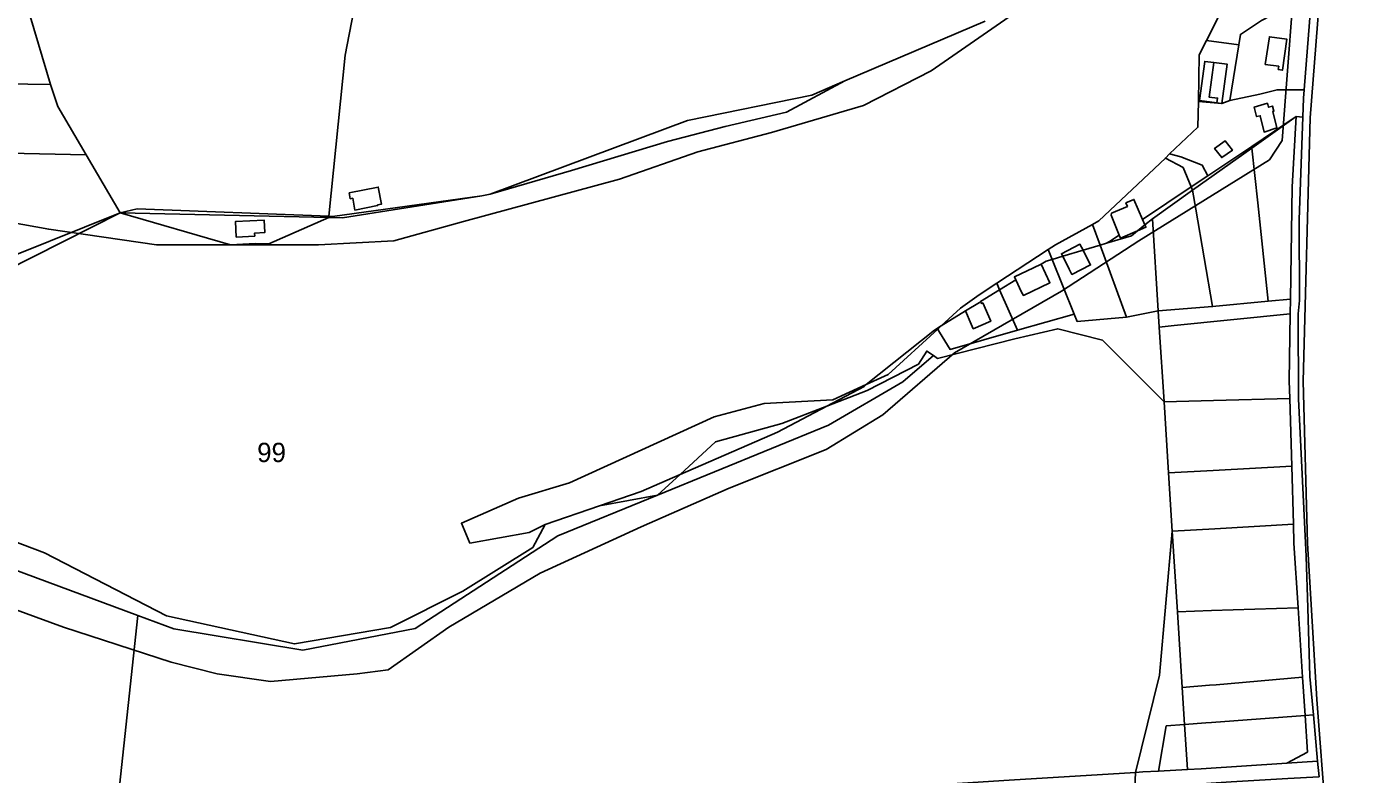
# Model space of a CAD drawing. Extents: x -537068 to -534056, y -1176840 to -1172401.
# Drawn here: x -535510.5 to -535168.8, y -1176578.1 to -1176384.5 of the extents above; entities that cross this region are included whole.
import ezdxf

# ---------------------------------------------------------------- set-up
doc = ezdxf.new("R2010")
doc.units = 0
for name, color, linetype in [('95560013', 7, 'Continuous'), ('95630013', 7, 'Continuous'), ('95640013', 7, 'Continuous'), ('95660013', 7, 'Continuous')]:
    doc.layers.add(name, color=color, linetype=linetype)

msp = doc.modelspace()

# ---------------------------------------------------------------- linework, layer by layer
at = {"layer": '95560013'}
for points in [[(-535481.85, -1176431.69), (-535486.24, -1176432.72), (-535495.01, -1176417.7), (-535502.3, -1176405.2), (-535504.23, -1176399.52), (-535511.62, -1176374.55), (-535501.24, -1176369.64), (-535467.02, -1176363.71), (-535431.92, -1176357.62), (-535424.35, -1176355.69), (-535420.92, -1176355.35), (-535427.94, -1176391.96), (-535432.2, -1176433.64)], [(-535511.62, -1176374.55), (-535504.23, -1176399.52), (-535562.67, -1176398.68)], [(-535495.01, -1176417.7), (-535595.37, -1176415.54), (-535577.58, -1176405.73), (-535562.67, -1176398.68), (-535504.23, -1176399.52), (-535502.3, -1176405.2)], [(-535495.01, -1176417.7), (-535486.24, -1176432.72), (-535522.77, -1176447.43), (-535520.14, -1176434.4), (-535519.96, -1176430.27), (-535571.1, -1176424.91), (-535618.53, -1176428.31), (-535595.37, -1176415.54)], [(-535419.44, -1176426.07), (-535426.94, -1176427.6), (-535426.66, -1176429.1), (-535426.01, -1176428.98), (-535425.44, -1176432.03), (-535419.58, -1176430.86), (-535419.61, -1176430.71), (-535418.55, -1176430.5)], [(-535428.71, -1176434.07), (-535432.24, -1176433.99), (-535432.2, -1176433.64), (-535431.24, -1176433.68), (-535392.59, -1176428.31)], [(-535523.63, -1176451.66), (-535522.77, -1176447.43), (-535486.24, -1176432.72)], [(-535481.85, -1176431.69), (-535432.2, -1176433.64), (-535432.24, -1176433.99), (-535486.24, -1176432.72)]]:
    msp.add_lwpolyline(points, close=True, dxfattribs=at)
msp.add_lwpolyline([(-535262.36, -1176383.13), (-535298.7, -1176398.63), (-535307.24, -1176402.28), (-535339.41, -1176408.87), (-535390.42, -1176427.96), (-535392.59, -1176428.31), (-535431.24, -1176433.68), (-535432.2, -1176433.64), (-535427.94, -1176391.96), (-535420.92, -1176355.35)], dxfattribs=at)
at = {"layer": '95630013'}
for points in [[(-535201.88, -1176381.84), (-535205.08, -1176388.14), (-535206.96, -1176391.84), (-535207.19, -1176403.93), (-535207.32, -1176410.61), (-535214.63, -1176417.52), (-535215.74, -1176418.57), (-535232.97, -1176434.86), (-535234.57, -1176435.74), (-535244.18, -1176441.03), (-535246.07, -1176442.27), (-535259.38, -1176450.99), (-535263.89, -1176453.95), (-535268.77, -1176457.43), (-535273.76, -1176462.03), (-535275.52, -1176463.11), (-535293.14, -1176477.21), (-535301.82, -1176481.16), (-535319.57, -1176482.1), (-535332.49, -1176485.54), (-535369.95, -1176502.58), (-535383.1, -1176506.55), (-535397.91, -1176513.07), (-535395.69, -1176518.21), (-535380.34, -1176515.47), (-535376.22, -1176513.36), (-535379.46, -1176519.34), (-535397.53, -1176530.66), (-535416.25, -1176540.06), (-535441.1, -1176544.28), (-535474.22, -1176537.07), (-535505.76, -1176520.73), (-535533.2, -1176510.4)], [(-535523.63, -1176451.66), (-535486.24, -1176432.72), (-535457.69, -1176441.02), (-535451.28, -1176440.64), (-535447.75, -1176440.73), (-535432.24, -1176433.99), (-535428.71, -1176434.07), (-535392.59, -1176428.31), (-535390.42, -1176427.96), (-535369.38, -1176421.83), (-535344.59, -1176414.25), (-535329.68, -1176410.43), (-535313.78, -1176406.71), (-535298.7, -1176398.63), (-535262.36, -1176383.13)], [(-535533.2, -1176510.4), (-535505.76, -1176520.73), (-535474.22, -1176537.07), (-535441.1, -1176544.28), (-535416.25, -1176540.06), (-535397.53, -1176530.66), (-535379.46, -1176519.34), (-535376.22, -1176513.36), (-535362.19, -1176508.54), (-535347.18, -1176505.79), (-535372.98, -1176516.36), (-535409.88, -1176540.34), (-535438.98, -1176545.89), (-535472.29, -1176540.41), (-535481.66, -1176536.93), (-535537.73, -1176516.12)]]:
    msp.add_lwpolyline(points, dxfattribs=at)
for points in [[(-535339.41, -1176408.87), (-535307.24, -1176402.28), (-535298.7, -1176398.63), (-535313.78, -1176406.71), (-535329.68, -1176410.43), (-535344.59, -1176414.25), (-535369.38, -1176421.83), (-535390.42, -1176427.96)], [(-535447.75, -1176440.73), (-535451.28, -1176440.64), (-535457.69, -1176441.02), (-535486.24, -1176432.72), (-535432.24, -1176433.99)], [(-535451.37, -1176438.77), (-535451.41, -1176437.98), (-535448.79, -1176437.86), (-535448.97, -1176434.63), (-535456.32, -1176434.98), (-535456.16, -1176439.02)], [(-535481.66, -1176536.93), (-535472.29, -1176540.41), (-535438.98, -1176545.89), (-535409.88, -1176540.34), (-535372.98, -1176516.36), (-535347.18, -1176505.79), (-535302.92, -1176487.67), (-535283.68, -1176476.52), (-535275.78, -1176469.69), (-535274.71, -1176470.43), (-535254.68, -1176465.39), (-535243.6, -1176462.73), (-535231.98, -1176465.74), (-535216.08, -1176481.68), (-535214.91, -1176500.06), (-535213.95, -1176515.16), (-535217.22, -1176552.4), (-535223.43, -1176577.55), (-535256.14, -1176579.59), (-535277.65, -1176580.92), (-535296.77, -1176582.11), (-535421.85, -1176589.87), (-535487.75, -1176593.96)], [(-535293.14, -1176477.21), (-535275.52, -1176463.11), (-535273.76, -1176462.03), (-535274.65, -1176462.84), (-535287.44, -1176474.62)], [(-535347.18, -1176505.79), (-535341.33, -1176500.46), (-535316.14, -1176489.48), (-535303.38, -1176482.75), (-535292.89, -1176478.68), (-535279.66, -1176471.94), (-535277.47, -1176468.51), (-535275.78, -1176469.69), (-535283.68, -1176476.52), (-535302.92, -1176487.67)], [(-535315, -1176487.27), (-535303.38, -1176482.75), (-535316.14, -1176489.48), (-535341.33, -1176500.46), (-535332.11, -1176492.04)], [(-535611.19, -1176513.92), (-535537.73, -1176516.12), (-535481.66, -1176536.93), (-535487.75, -1176593.96), (-535547.63, -1176597.67), (-535617.46, -1176602.04), (-535616.99, -1176606.16), (-535547.67, -1176601.79), (-535488.18, -1176598.05), (-535496.14, -1176672.63), (-535510.43, -1176678.69), (-535538.74, -1176685.61), (-535560.3, -1176696.02), (-535567.5, -1176700.1), (-535587.32, -1176690.88), (-535593.03, -1176689.8), (-535608.35, -1176682.47), (-535631.81, -1176671.18), (-535642.41, -1176641.9), (-535625.41, -1176591.75), (-535625.2, -1176543.89)], [(-535616.99, -1176606.16), (-535617.46, -1176602.04), (-535547.63, -1176597.67), (-535487.75, -1176593.96), (-535421.85, -1176589.87), (-535296.77, -1176582.11), (-535277.65, -1176580.92), (-535256.14, -1176579.59), (-535223.43, -1176577.55), (-535223.63, -1176581.58), (-535224.99, -1176581.66), (-535236.23, -1176582.36), (-535246.06, -1176582.97), (-535421.6, -1176593.86), (-535488.18, -1176598.05), (-535547.67, -1176601.79)]]:
    msp.add_lwpolyline(points, close=True, dxfattribs=at)
at = {"layer": '95640013'}
for points in [[(-535168.84, -1176287.98), (-535178.27, -1176408.14), (-535180.12, -1176476.29), (-535178.97, -1176518.25), (-535176.57, -1176558.65), (-535171.92, -1176619.39)], [(-535175.97, -1176578.68), (-535176.34, -1176574.66), (-535177.43, -1176562.68), (-535178.34, -1176552.77), (-535178.9, -1176534.97), (-535179.3, -1176521.64), (-535181.32, -1176480.84), (-535181.35, -1176458.92), (-535181.06, -1176455.43), (-535181.08, -1176434.43), (-535180.14, -1176407.98), (-535179.97, -1176403.1), (-535179.8, -1176400.89), (-535177.92, -1176376.77)]]:
    msp.add_lwpolyline(points, dxfattribs=at)
for points in [[(-535177.92, -1176376.77), (-535188.56, -1176381.77), (-535190.84, -1176383), (-535196.3, -1176386.58), (-535196.74, -1176389.27), (-535205.08, -1176388.14), (-535201.88, -1176381.84), (-535191.43, -1176380.38), (-535189.63, -1176379.33), (-535177.7, -1176373.96)], [(-535196.74, -1176389.27), (-535196.3, -1176386.58), (-535190.84, -1176383), (-535188.56, -1176381.77), (-535177.92, -1176376.77), (-535179.8, -1176400.89), (-535182.66, -1176400.88), (-535186.83, -1176400.9), (-535191.31, -1176402.04), (-535199.02, -1176403.71)], [(-535205.08, -1176388.14), (-535196.74, -1176389.27), (-535199.02, -1176403.71), (-535201.16, -1176404.46), (-535199.74, -1176394.28), (-535203.22, -1176393.84), (-535205.56, -1176393.55), (-535206.94, -1176403.67), (-535202.41, -1176404.29), (-535201.16, -1176404.46), (-535207.19, -1176403.93), (-535206.96, -1176391.84)], [(-535186.54, -1176395.62), (-535185.43, -1176395.86), (-535184.31, -1176387.78), (-535188.83, -1176387.17), (-535189.87, -1176394.33), (-535186.4, -1176394.8)], [(-535186.4, -1176394.8), (-535189.87, -1176394.33), (-535188.83, -1176387.17), (-535184.31, -1176387.78), (-535185.43, -1176395.86), (-535186.54, -1176395.62)], [(-535206.94, -1176403.67), (-535205.56, -1176393.55), (-535203.22, -1176393.84), (-535204.43, -1176402.78), (-535202.24, -1176403.07), (-535202.41, -1176404.29)], [(-535199.74, -1176394.28), (-535201.16, -1176404.46), (-535202.41, -1176404.29), (-535202.24, -1176403.07), (-535204.43, -1176402.78), (-535203.22, -1176393.84)], [(-535179.97, -1176403.1), (-535180.14, -1176407.98), (-535181.86, -1176407.84), (-535193.38, -1176415.55), (-535204.79, -1176423.18), (-535206.18, -1176420.42), (-535211.73, -1176418.24), (-535214.63, -1176417.52), (-535207.32, -1176410.61), (-535207.19, -1176403.93), (-535201.16, -1176404.46), (-535199.02, -1176403.71), (-535191.31, -1176402.04), (-535186.83, -1176400.9), (-535182.66, -1176400.88), (-535179.8, -1176400.89)], [(-535190.2, -1176411.86), (-535191.18, -1176407.62), (-535192.15, -1176407.84), (-535192.8, -1176405.44), (-535189.32, -1176404.38), (-535189.04, -1176405.43), (-535188.03, -1176405.11), (-535187.66, -1176406.43), (-535187.91, -1176406.5), (-535186.9, -1176410.78)], [(-535189.32, -1176404.38), (-535192.8, -1176405.44), (-535192.15, -1176407.84), (-535191.18, -1176407.62), (-535190.2, -1176411.86), (-535186.9, -1176410.78), (-535187.91, -1176406.5), (-535187.66, -1176406.43), (-535188.03, -1176405.11), (-535189.04, -1176405.43)], [(-535181.86, -1176407.84), (-535193.33, -1176415.99), (-535193.38, -1176415.55)], [(-535181.86, -1176407.84), (-535182.92, -1176426.05), (-535183.35, -1176455.05), (-535189.17, -1176455.61), (-535191.84, -1176430.14), (-535193.33, -1176415.99)], [(-535177.43, -1176562.68), (-535179.58, -1176562.84), (-535180.22, -1176552.91), (-535181.38, -1176534.99), (-535182.46, -1176518.26), (-535182.6, -1176513.31), (-535183.03, -1176498.34), (-535183.53, -1176480.82), (-535183.66, -1176476.24), (-535183.4, -1176458.9), (-535183.35, -1176455.05), (-535182.92, -1176426.05), (-535181.86, -1176407.84), (-535180.14, -1176407.98), (-535181.08, -1176434.43), (-535181.06, -1176455.43), (-535181.35, -1176458.92), (-535181.32, -1176480.84), (-535179.3, -1176521.64), (-535178.9, -1176534.97), (-535178.34, -1176552.77)], [(-535204.79, -1176423.18), (-535193.38, -1176415.55), (-535193.33, -1176415.99), (-535208.69, -1176426.9), (-535209.05, -1176426.04)], [(-535191.84, -1176430.14), (-535189.17, -1176455.61), (-535203.54, -1176456.99), (-535207.85, -1176431.83), (-535208.69, -1176426.9), (-535193.33, -1176415.99)], [(-535201.13, -1176418.47), (-535203.02, -1176416.07), (-535200.22, -1176414.13), (-535198.4, -1176416.55)], [(-535200.22, -1176414.13), (-535203.02, -1176416.07), (-535201.13, -1176418.47), (-535198.4, -1176416.55)], [(-535227.68, -1176438.5), (-535230.16, -1176440.16), (-535230.97, -1176440.62), (-535232.61, -1176441.11), (-535234.57, -1176435.74), (-535232.97, -1176434.86), (-535215.74, -1176418.57), (-535211.16, -1176421), (-535209.05, -1176426.04), (-535221.64, -1176434.46), (-535223.89, -1176429.27), (-535225.94, -1176430.16), (-535225.55, -1176431.07), (-535229.66, -1176432.87), (-535229.8, -1176433.39)], [(-535204.79, -1176423.18), (-535209.05, -1176426.04), (-535211.16, -1176421), (-535215.74, -1176418.57), (-535214.63, -1176417.52), (-535211.73, -1176418.24), (-535206.18, -1176420.42)], [(-535426.66, -1176429.1), (-535426.94, -1176427.6), (-535419.44, -1176426.07), (-535418.55, -1176430.5), (-535419.61, -1176430.71), (-535419.58, -1176430.86), (-535425.44, -1176432.03), (-535426.01, -1176428.98)], [(-535209.05, -1176426.04), (-535208.69, -1176426.9), (-535219.1, -1176434.29), (-535221.03, -1176435.85), (-535221.64, -1176434.46)], [(-535221.64, -1176434.46), (-535221.03, -1176435.85), (-535222.94, -1176437.41), (-535227.34, -1176439.31), (-535227.68, -1176438.5), (-535229.8, -1176433.39), (-535229.66, -1176432.87), (-535225.55, -1176431.07), (-535225.94, -1176430.16), (-535223.89, -1176429.27)], [(-535217.59, -1176458.09), (-535219.1, -1176434.29), (-535208.69, -1176426.9), (-535207.85, -1176431.83), (-535203.54, -1176456.99)], [(-535451.37, -1176438.77), (-535456.16, -1176439.02), (-535456.32, -1176434.98), (-535448.97, -1176434.63), (-535448.79, -1176437.86), (-535451.41, -1176437.98)], [(-535242.31, -1176444), (-535245.04, -1176444.81), (-535246.07, -1176442.27), (-535244.18, -1176441.03), (-535234.57, -1176435.74), (-535232.61, -1176441.11), (-535237.03, -1176442.43), (-535237.84, -1176440.87), (-535242.65, -1176443.34)], [(-535219.1, -1176434.29), (-535217.59, -1176458.09), (-535225.8, -1176459.71), (-535232.61, -1176441.11), (-535230.97, -1176440.62), (-535224.53, -1176438.7), (-535222.94, -1176437.41), (-535220.76, -1176436.47), (-535221.03, -1176435.85)], [(-535222.94, -1176437.41), (-535221.03, -1176435.85), (-535220.76, -1176436.47)], [(-535227.68, -1176438.5), (-535227.34, -1176439.31), (-535222.94, -1176437.41), (-535224.53, -1176438.7), (-535230.97, -1176440.62), (-535230.16, -1176440.16)], [(-535258.62, -1176452.69), (-535259.38, -1176450.99), (-535246.07, -1176442.27), (-535245.04, -1176444.81), (-535246.6, -1176445.28), (-535247.89, -1176446.07), (-535249.84, -1176446.99), (-535254.8, -1176449.32), (-535254.43, -1176450.11)], [(-535239.32, -1176458.95), (-535245.04, -1176444.81), (-535242.31, -1176444), (-535240.59, -1176447.35), (-535239.9, -1176448.68), (-535235.1, -1176446.22), (-535235.78, -1176444.88), (-535237.03, -1176442.43), (-535232.61, -1176441.11), (-535225.8, -1176459.71), (-535238.54, -1176460.88)], [(-535237.84, -1176440.87), (-535237.03, -1176442.43), (-535242.31, -1176444), (-535242.65, -1176443.34)], [(-535235.78, -1176444.88), (-535235.1, -1176446.22), (-535239.9, -1176448.68), (-535240.59, -1176447.35), (-535242.31, -1176444), (-535237.03, -1176442.43)], [(-535245.04, -1176444.81), (-535239.32, -1176458.95), (-535253.98, -1176463.11), (-535258.62, -1176452.69), (-535254.43, -1176450.11), (-535252.95, -1176453.31), (-535252.48, -1176454.12), (-535245.63, -1176450.83), (-535247.89, -1176446.07), (-535246.6, -1176445.28)], [(-535249.84, -1176446.99), (-535247.89, -1176446.07), (-535245.63, -1176450.83), (-535252.48, -1176454.12), (-535252.95, -1176453.31), (-535254.43, -1176450.11), (-535254.8, -1176449.32)], [(-535274.17, -1176463.62), (-535274.65, -1176462.84), (-535273.76, -1176462.03), (-535267.45, -1176458.14), (-535266, -1176461.52), (-535265.46, -1176462.76), (-535260.94, -1176460.81), (-535261.45, -1176459.57), (-535263.01, -1176456.05), (-535263.35, -1176456.2), (-535263.55, -1176455.73), (-535258.62, -1176452.69), (-535253.98, -1176463.11), (-535271.44, -1176468.07)], [(-535273.76, -1176462.03), (-535268.77, -1176457.43), (-535263.89, -1176453.95), (-535259.38, -1176450.99), (-535258.62, -1176452.69), (-535263.55, -1176455.73), (-535263.84, -1176455.91), (-535267.45, -1176458.14)], [(-535263.55, -1176455.73), (-535263.35, -1176456.2), (-535263.01, -1176456.05), (-535261.45, -1176459.57), (-535260.94, -1176460.81), (-535265.46, -1176462.76), (-535266, -1176461.52), (-535267.45, -1176458.14), (-535263.84, -1176455.91)], [(-535183.4, -1176458.9), (-535213.44, -1176461.92), (-535217.32, -1176462.31), (-535217.59, -1176458.09), (-535203.54, -1176456.99), (-535189.17, -1176455.61), (-535183.35, -1176455.05)], [(-535217.32, -1176462.31), (-535216.08, -1176481.68), (-535231.98, -1176465.74), (-535243.6, -1176462.73), (-535254.68, -1176465.39), (-535274.71, -1176470.43), (-535275.78, -1176469.69), (-535277.47, -1176468.51), (-535279.66, -1176471.94), (-535292.89, -1176478.68), (-535303.38, -1176482.75), (-535293.69, -1176477.65), (-535293.14, -1176477.21), (-535287.44, -1176474.62), (-535274.65, -1176462.84), (-535274.17, -1176463.62), (-535271.44, -1176468.07), (-535253.98, -1176463.11), (-535239.32, -1176458.95), (-535238.54, -1176460.88), (-535225.8, -1176459.71), (-535217.59, -1176458.09)], [(-535183.4, -1176458.9), (-535183.66, -1176476.24), (-535183.53, -1176480.82), (-535203.28, -1176481.34), (-535216.08, -1176481.68), (-535217.32, -1176462.31), (-535213.44, -1176461.92)], [(-535332.49, -1176485.54), (-535319.57, -1176482.1), (-535301.82, -1176481.16), (-535293.14, -1176477.21), (-535293.69, -1176477.65), (-535303.38, -1176482.75), (-535315, -1176487.27), (-535332.11, -1176492.04), (-535341.33, -1176500.46), (-535351.35, -1176504.82), (-535362.19, -1176508.54), (-535376.22, -1176513.36), (-535380.34, -1176515.47), (-535395.69, -1176518.21), (-535397.91, -1176513.07), (-535383.1, -1176506.55), (-535369.95, -1176502.58)], [(-535214.91, -1176500.06), (-535216.08, -1176481.68), (-535203.28, -1176481.34), (-535183.53, -1176480.82), (-535183.03, -1176498.34), (-535203.37, -1176499.44)], [(-535182.6, -1176513.31), (-535202.91, -1176514.51), (-535213.95, -1176515.16), (-535214.91, -1176500.06), (-535203.37, -1176499.44), (-535183.03, -1176498.34)], [(-535362.19, -1176508.54), (-535351.35, -1176504.82), (-535341.33, -1176500.46), (-535347.18, -1176505.79)], [(-535221.6, -1176577.44), (-535223.43, -1176577.55), (-535217.22, -1176552.4), (-535213.95, -1176515.16), (-535212.62, -1176535.96), (-535211.37, -1176555.62), (-535210.76, -1176565.18), (-535215.53, -1176565.53), (-535217.53, -1176577.23)], [(-535213.95, -1176515.16), (-535202.91, -1176514.51), (-535182.6, -1176513.31), (-535182.46, -1176518.26), (-535181.38, -1176534.99), (-535203.82, -1176535.69), (-535212.62, -1176535.96)], [(-535180.22, -1176552.91), (-535202.56, -1176554.85), (-535204.31, -1176555), (-535211.37, -1176555.62), (-535212.62, -1176535.96), (-535203.82, -1176535.69), (-535181.38, -1176534.99)], [(-535205.27, -1176564.76), (-535210.76, -1176565.18), (-535211.37, -1176555.62), (-535204.31, -1176555), (-535202.56, -1176554.85), (-535180.22, -1176552.91), (-535179.58, -1176562.84), (-535203.79, -1176564.65)], [(-535210.76, -1176565.18), (-535205.27, -1176564.76), (-535203.79, -1176564.65), (-535179.58, -1176562.84), (-535178.97, -1176572.31), (-535184.3, -1176575.17), (-535206.44, -1176576.6), (-535210.02, -1176576.83)], [(-535178.97, -1176572.31), (-535179.58, -1176562.84), (-535177.43, -1176562.68), (-535176.34, -1176574.66), (-535184.3, -1176575.17)], [(-535210.76, -1176565.18), (-535210.02, -1176576.83), (-535217.53, -1176577.23), (-535215.53, -1176565.53)], [(-535223.63, -1176581.58), (-535223.43, -1176577.55), (-535221.6, -1176577.44), (-535217.53, -1176577.23), (-535210.02, -1176576.83), (-535206.44, -1176576.6), (-535184.3, -1176575.17), (-535176.34, -1176574.66), (-535175.97, -1176578.68), (-535184.02, -1176579.16), (-535198.74, -1176580.03), (-535211.52, -1176580.83), (-535215.99, -1176581.11)]]:
    msp.add_lwpolyline(points, close=True, dxfattribs=at)
at = {"layer": '95660013'}
for points in [[(-535168.84, -1176287.98), (-535178.27, -1176408.14), (-535180.12, -1176476.29), (-535178.97, -1176518.25), (-535176.57, -1176558.65), (-535171.92, -1176619.39)], [(-535530.87, -1176529), (-535500.87, -1176540), (-535473, -1176549), (-535461.12, -1176552), (-535447.31, -1176554), (-535424.87, -1176552), (-535416.87, -1176551), (-535401.12, -1176540), (-535377.5, -1176526), (-535351.37, -1176514), (-535328.62, -1176504), (-535303.5, -1176494), (-535288.81, -1176485), (-535270.31, -1176469), (-535242.62, -1176453), (-535222.62, -1176440), (-535188.81, -1176419), (-535185.5, -1176414), (-535181.5, -1176361)], [(-535181.5, -1176361), (-535185.5, -1176414), (-535188.81, -1176419), (-535222.62, -1176440), (-535242.62, -1176453), (-535270.31, -1176469), (-535288.81, -1176485), (-535303.5, -1176494), (-535328.62, -1176504), (-535351.37, -1176514), (-535377.5, -1176526), (-535401.12, -1176540), (-535416.87, -1176551), (-535424.87, -1176552), (-535447.31, -1176554), (-535461.12, -1176552), (-535473, -1176549), (-535500.87, -1176540), (-535530.87, -1176529)], [(-535256.12, -1176382), (-535276.37, -1176396), (-535293.81, -1176405), (-535317.69, -1176412), (-535336.69, -1176417), (-535357, -1176424), (-535397.37, -1176435), (-535415.37, -1176440), (-535434.87, -1176441), (-535476.81, -1176441), (-535504.69, -1176437), (-535514.79, -1176435.12)], [(-535514.79, -1176435.12), (-535504.69, -1176437), (-535476.81, -1176441), (-535434.87, -1176441), (-535415.37, -1176440), (-535397.37, -1176435), (-535357, -1176424), (-535336.69, -1176417), (-535317.69, -1176412), (-535293.81, -1176405), (-535276.37, -1176396), (-535256.12, -1176382)]]:
    msp.add_lwpolyline(points, dxfattribs=at)

# ---------------------------------------------------------------- texts
msp.add_text('99', height=5, rotation=360, dxfattribs=at).set_placement((-535450.75, -1176497.25))

doc.saveas('drawing.dxf')
